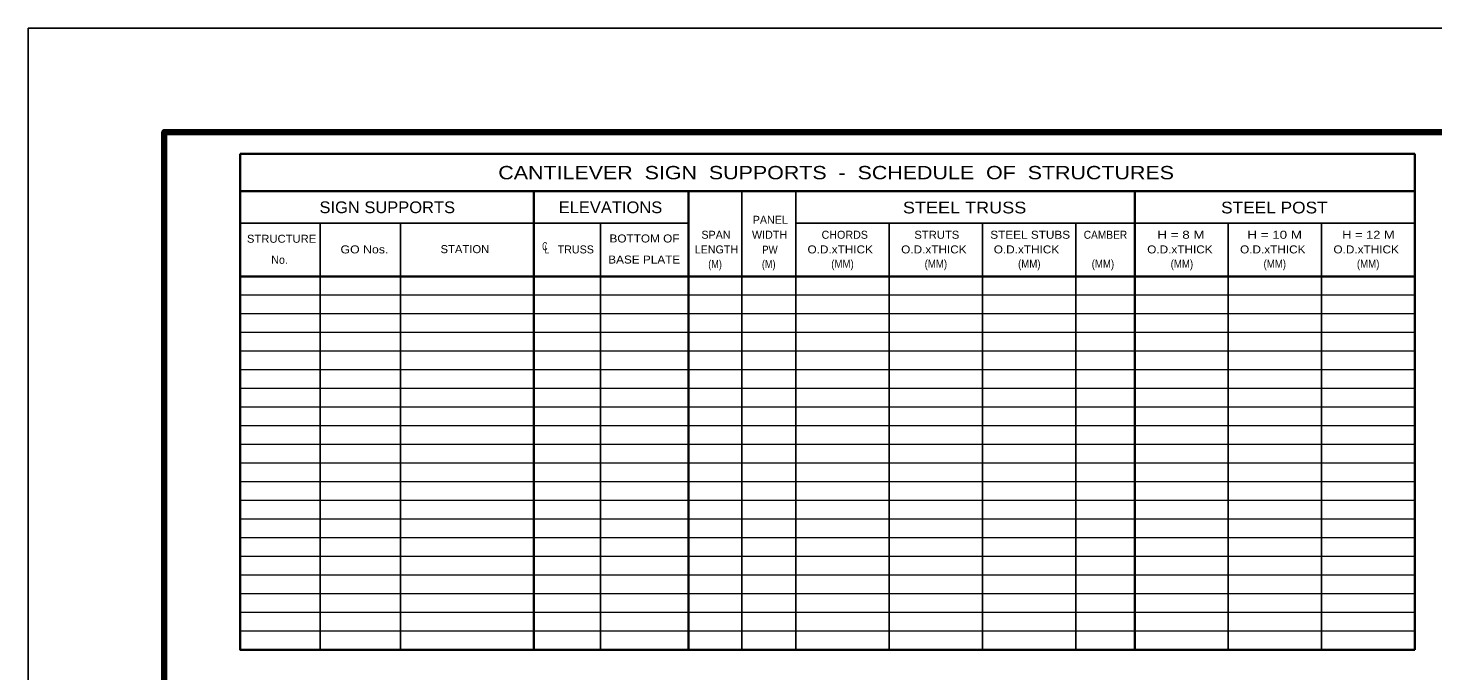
# Model space of a CAD drawing. Extents: x 312601.858 to 312602.699, y 144420.109 to 144420.704.
# Drawn here: x 312601.858 to 312602.384, y 144420.462 to 144420.704 of the extents above; entities that cross this region are included whole.
import ezdxf
from ezdxf.enums import TextEntityAlignment as Align

# ---------------------------------------------------------------- set-up
doc = ezdxf.new("R2010")
doc.units = 0
doc.header["$LTSCALE"] = 0.0012
for name, color, linetype, lineweight in [('1', 7, 'Continuous', 13), ('2', 7, 'Continuous', 13), ('39', 7, 'Continuous', 13)]:
    doc.layers.add(name, color=color, linetype=linetype, lineweight=lineweight)

msp = doc.modelspace()

# ---------------------------------------------------------------- linework, layer by layer
at = {"layer": '1', "lineweight": 35}
for p, q in [((312601.9373, 144420.6564), (312601.9373, 144420.4704)), ((312602.3775, 144420.6564), (312601.9373, 144420.6564)), ((312602.3775, 144420.6564), (312602.3775, 144420.4704)), ((312602.0473, 144420.6424), (312602.0473, 144420.4704)), ((312602.1053, 144420.6424), (312602.1053, 144420.4704)), ((312602.2725, 144420.6424), (312602.2725, 144420.4704))]:
    msp.add_line(p, q, dxfattribs=at)
at = {"layer": '1', "lineweight": 25}
for p, q in [((312602.1253, 144420.6424), (312602.1253, 144420.4704)), ((312602.1455, 144420.6424), (312602.1455, 144420.4704)), ((312602.1053, 144420.6304), (312601.9373, 144420.6304)), ((312601.9673, 144420.6304), (312601.9673, 144420.4704)), ((312601.9973, 144420.6304), (312601.9973, 144420.4704)), ((312602.0723, 144420.6304), (312602.0723, 144420.4704)), ((312602.3775, 144420.6304), (312602.1455, 144420.6304)), ((312602.1805, 144420.6304), (312602.1805, 144420.4704)), ((312602.2155, 144420.6304), (312602.2155, 144420.4704)), ((312602.2505, 144420.6304), (312602.2505, 144420.4704)), ((312602.3075, 144420.6304), (312602.3075, 144420.4704)), ((312602.3425, 144420.6304), (312602.3425, 144420.4704))]:
    msp.add_line(p, q, dxfattribs=at)
at = {"layer": '1'}
msp.add_line((312602.0723, 144420.6268), (312602.0723, 144420.4976), dxfattribs=at)
at = {"layer": '1', "lineweight": 35}
for points in [[(312602.3775, 144420.6424), (312602.1455, 144420.6424), (312601.9373, 144420.6424)], [(312602.3775, 144420.6104), (312602.1455, 144420.6104), (312601.9373, 144420.6104)], [(312602.3775, 144420.4704), (312602.1455, 144420.4704), (312601.9372, 144420.4704)]]:
    msp.add_lwpolyline(points, dxfattribs=at)
at = {"layer": '1'}
for points in [[(312602.3775, 144420.6034), (312602.1455, 144420.6034), (312601.9373, 144420.6034)], [(312602.3775, 144420.5964), (312602.1455, 144420.5964), (312601.9373, 144420.5964)], [(312602.3775, 144420.5894), (312602.1455, 144420.5894), (312601.9373, 144420.5894)], [(312602.3775, 144420.5824), (312602.1455, 144420.5824), (312601.9373, 144420.5824)], [(312602.3775, 144420.5754), (312602.1455, 144420.5754), (312601.9373, 144420.5754)], [(312602.3775, 144420.5684), (312602.1455, 144420.5684), (312601.9373, 144420.5684)], [(312602.3775, 144420.5614), (312602.1455, 144420.5614), (312601.9373, 144420.5614)], [(312602.3775, 144420.5544), (312602.1455, 144420.5544), (312601.9373, 144420.5544)], [(312602.3775, 144420.5474), (312602.1455, 144420.5474), (312601.9373, 144420.5474)], [(312602.3775, 144420.5404), (312602.1455, 144420.5404), (312601.9373, 144420.5404)], [(312602.3775, 144420.5334), (312602.1455, 144420.5334), (312601.9373, 144420.5334)], [(312602.3775, 144420.5264), (312602.1455, 144420.5264), (312601.9373, 144420.5264)], [(312602.3775, 144420.5194), (312602.1455, 144420.5194), (312601.9373, 144420.5194)], [(312602.3775, 144420.5124), (312602.1455, 144420.5124), (312601.9373, 144420.5124)], [(312602.3775, 144420.5054), (312602.1455, 144420.5054), (312601.9373, 144420.5054)], [(312602.3775, 144420.4984), (312602.1455, 144420.4984), (312601.9373, 144420.4984)], [(312602.3775, 144420.4914), (312602.1455, 144420.4914), (312601.9373, 144420.4914)], [(312602.3775, 144420.4844), (312602.1455, 144420.4844), (312601.9373, 144420.4844)], [(312602.3775, 144420.4774), (312602.1455, 144420.4774), (312601.9373, 144420.4774)]]:
    msp.add_lwpolyline(points, dxfattribs=at)
at = {"layer": '39', "lineweight": 25}
for p, q in [((312601.8578, 144420.7035), (312602.6988, 144420.7035)), ((312601.8578, 144420.1095), (312601.8578, 144420.7035))]:
    msp.add_line(p, q, dxfattribs=at)
at = {"layer": '39', "lineweight": 158}
msp.add_lwpolyline([(312601.9088, 144420.1247), (312601.9088, 144420.6645), (312602.6838, 144420.6645)], dxfattribs=at)

# ---------------------------------------------------------------- texts
at = {"layer": '2'}
for s, height, width, p in [('CANTILEVER  SIGN  SUPPORTS  -  SCHEDULE  OF  STRUCTURES  ', 0.005, 1.2, (312602.16285, 144420.6468)), ('SIGN SUPPORTS', 0.0044, 1.05, (312601.9924, 144420.6341)), ('ELEVATIONS', 0.0044, 1.05, (312602.07605, 144420.6341)), ('STEEL TRUSS ', 0.0044, 1.15, (312602.2097, 144420.634)), ('STEEL POST', 0.0044, 1.1, (312602.32485, 144420.634)), ('STRUCTURE', 0.003, 1.05, (312601.9528, 144420.623)), ('BOTTOM OF', 0.003, 1.1, (312602.0888, 144420.6231)), ('STRUTS', 0.003, 1.05, (312602.19835, 144420.6245)), ('STEEL STUBS', 0.003, 1.1, (312602.23335, 144420.6245)), ('CAMBER', 0.003, 0.95, (312602.26155, 144420.6245)), ('H = 8 M', 0.003, 1.25, (312602.28985, 144420.6245)), ('H = 10 M', 0.003, 1.25, (312602.32495, 144420.6245)), ('H = 12 M', 0.003, 1.2, (312602.3601, 144420.6245)), ('GO Nos.', 0.003, 1.15, (312601.98385, 144420.619)), ('STATION', 0.003, 1.05, (312602.0215, 144420.6191)), ('C', 0.003, 0.7, (312602.05145, 144420.6202)), ('L', 0.003, 0.75, (312602.05225, 144420.619)), ('PW', 0.003, 0.9, (312602.1358, 144420.6189)), ('O.D.xTHICK', 0.003, 1.1, (312602.16215, 144420.619)), ('O.D.xTHICK', 0.003, 1.1, (312602.19725, 144420.619)), ('O.D.xTHICK', 0.003, 1.1, (312602.23195, 144420.619)), ('O.D.xTHICK', 0.003, 1.1, (312602.28945, 144420.619)), ('O.D.xTHICK', 0.003, 1.1, (312602.32425, 144420.619)), ('O.D.xTHICK', 0.003, 1.1, (312602.35925, 144420.619)), ('BASE PLATE', 0.003, 1.1, (312602.0887, 144420.6152)), ('(M)', 0.003, 0.85, (312602.11525, 144420.6135)), ('(M)', 0.003, 0.85, (312602.13535, 144420.6135)), ('(MM)', 0.003, 0.9, (312602.163, 144420.6136)), ('(MM)', 0.003, 0.9, (312602.198, 144420.6136)), ('(MM)', 0.003, 0.9, (312602.233, 144420.6136)), ('(MM)', 0.003, 0.9, (312602.2606, 144420.6136)), ('(MM)', 0.003, 0.9, (312602.2902, 144420.6136)), ('(MM)', 0.003, 0.9, (312602.325, 144420.6136)), ('(MM)', 0.003, 0.9, (312602.36, 144420.6136))]:
    msp.add_text(s, height=height, dxfattribs=dict(at, width=width)).set_placement(p, align=Align.CENTER)
for s, p in [('PANEL', (312602.13595, 144420.6301)), ('SPAN', (312602.1156, 144420.6245)), ('WIDTH', (312602.13565, 144420.6245)), ('CHORDS', (312602.16385, 144420.6245)), ('TRUSS', (312602.06305, 144420.619)), ('LENGTH', (312602.11575, 144420.619)), ('No.', (312601.95205, 144420.6151))]:
    msp.add_text(s, height=0.003, dxfattribs=at).set_placement(p, align=Align.CENTER)

doc.saveas('drawing.dxf')
